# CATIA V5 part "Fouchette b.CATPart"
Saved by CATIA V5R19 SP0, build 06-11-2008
Part number: Fouchette b
Bounding box of the stored display mesh (mm): x -5 to 25, y -62.897 to 66.305, z -40 to 76.539
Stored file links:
  F:\CFAO\Hberriche\Fouchette b.CATPart
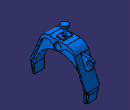
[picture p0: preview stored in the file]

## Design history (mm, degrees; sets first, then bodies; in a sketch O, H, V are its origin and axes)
Body1 (main body)
  Sketch1 on yz-plane, origin (0, 0, 0), H (0, 1, 0), V (0, 0, 1)
    line L1 (-54.7472, -20) -> (-54.7472, -40)
    point P1 (-54.7472, -20)
    point P2 (-54.7472, -40)
    point P3 (55.0096, -26.2979)
    arc A1 centre (0, -27) radius 55.1929 from (0, 28.1929) to (-54.7472, -20) ccw
    point P4 (0, -27)
    point P5 (-54.7472, -20)
    line L2 (-54.7472, -40) -> (-59.7472, -40)
    point P6 (-59.7472, -40)
    line L3 (-59.7472, -40) -> (-63.2737, -20)
    point P7 (-63.2737, -20)
    line L4 (-63.2737, -20) -> (-32.7996, 53.0392)
    point P8 (-32.7996, 53.0392)
    line L5 (-32.7996, 53.0392) -> (0, 53.0392)
    point P9 (-32.7996, 53.0392)
    axis line L6 (0, 72.9256) -> (0, -136.9568)
    point P10 (0, 72.9256)
    point P12 (0, 53.0392)
    point P13 (0, 28.1929)
    point P14 (0, 0)
    construction line L7 through (0, 0) direction (0, 1)
    point P17 (54.7472, -20)
    point P18 (54.7472, -40)
    point P20 (54.7472, -20)
    point P21 (59.7472, -40)
    point P22 (63.2737, -20)
    point P23 (32.7996, 53.0392)
    point P24 (32.7996, 53.0392)
    point P25 (0, 53.0392)
    point P26 (0, 28.1929)
    line L8 (54.7472, -20) -> (54.7472, -40)
    arc A2 centre (0, -27) radius 55.1929 from (0, 28.1929) to (54.7472, -20) cw
    line L9 (54.7472, -40) -> (59.7472, -40)
    line L10 (59.7472, -40) -> (63.2737, -20)
    line L11 (63.2737, -20) -> (32.7996, 53.0392)
    line L12 (32.7996, 53.0392) -> (0, 53.0392)
    distance P4 O = 27
    length L1 = 20
    radius A1 = 55.1929
    angle L3 L2 = 100
    length L2 = 5
    distance H L2 = 40
    distance P7 H = 20
    vertical: L1 V, L6 V
    coincidence: P4 V, P5 P1, P9 P8, P10 V, L6 P12, L6 P13, P12 P25, P13 P26, P17 P20, P23 P24
    horizontal: L2 H, L5 H
    symmetry: O P14 L6, V L7 L6, P1 P17 L6, P2 P18 L6, P5 P20 L6, P6 P21 L6, P7 P22 L6, P8 P23 L6, P9 P24 L6, P12 P25 L6, P13 P26 L6, L1 L8 L6, A1 A2 L6, L2 L9 L6, L3 L10 L6, L4 L11 L6, L5 L12 L6
  Pad1: profile Sketch1, direction (1, 0, 0), length 20
  Fillet1: radius 20, on edge [face of Pad1 from Sketch1.L4 | face of Pad1 from Sketch1.L5]; edge [face of Pad1 from Sketch1.L12 | face of Pad1 from Sketch1.L11]
  Fillet2: radius 10, on edge [face of Pad1 from Sketch1.L11 | face of Pad1 from Sketch1.L10]; edge [face of Pad1 from Sketch1.L3 | face of Pad1 from Sketch1.L4]
  Sketch2 on start face of Pad1, origin (0, 0, 0), H (0, -1, 0), V (0, 0, 1)
    axis line L1 (0, 18.2812) -> (0, -60.1212)
    point P1 (0, 18.2812)
    point P3 (-57.7472, -22)
    line L2 (-57.7472, -22) -> (-54.7472, -22)
    line L3 (-54.7472, -22) -> (-54.7472, -40)
    line L4 (-54.7472, -40) -> (-57.7472, -40)
    line L5 (-57.7472, -40) -> (-57.7472, -22)
    point P4 (-54.7472, -22)
    point P5 (-54.7472, -40)
    point P6 (-57.7472, -40)
    reference projected line E1 (-54.7472, -20) -> (-54.7472, -40) from edge [start face of Pad1 | face of Pad1 from Sketch1.L8]
    reference projected line E2 (-54.7472, -40) -> (-59.7472, -40) from edge [start face of Pad1 | face of Pad1 from Sketch1.L9]
    point P7 (57.7472, -22)
    point P8 (54.7472, -22)
    point P9 (54.7472, -40)
    point P10 (57.7472, -40)
    line L6 (57.7472, -22) -> (54.7472, -22)
    line L7 (54.7472, -22) -> (54.7472, -40)
    line L8 (54.7472, -40) -> (57.7472, -40)
    line L9 (57.7472, -40) -> (57.7472, -22)
    length L5 = 18
    length L2 = 3
    coincidence: P1 V, E1 L3, E2 L4
    vertical: L1 V, L3 V, L5 V
    horizontal: L2 H, L4 H
    symmetry: P3 P7 L1, P4 P8 L1, P5 P9 L1, P6 P10 L1, L2 L6 L1, L3 L7 L1, L4 L8 L1, L5 L9 L1
  Pad2: profile Sketch2, direction (-1, 0, 0), length 1.5
  Chamfer1: length 1, angle 45, on edge [start face of Pad1 | face of Pad2 from Sketch2.L5]; edge [start face of Pad1 | face of Pad2 from Sketch2.L9]
  Chamfer2: length 1, angle 45, on edge [face of Pad2 from Sketch2.L6 | start face of Pad1]; edge [face of Pad2 from Sketch2.L2 | start face of Pad1]
  Sketch3 on end face of Pad1, origin (20, 0, 0), H (0, 1, 0), V (0, 0, 1)
    point P1 (-57.7472, -22)
    line L1 (-57.7472, -22) -> (-54.7472, -22)
    line L2 (-54.7472, -22) -> (-54.7472, -40)
    line L3 (-54.7472, -40) -> (-57.7472, -40)
    line L4 (-57.7472, -40) -> (-57.7472, -22)
    point P2 (-54.7472, -22)
    point P3 (-54.7472, -40)
    point P4 (-57.7472, -40)
    reference projected line E1 (-54.7472, -40) -> (-54.7472, -20) from edge [face of Pad2 | end face of Pad1]
    reference projected line E2 (-59.7472, -40) -> (-54.7472, -40) from edge [face of Pad2 | end face of Pad1]
    axis line L5 (0, 14.1805) -> (0, -71.2709)
    point P5 (0, 14.1805)
    point P7 (57.7472, -22)
    point P8 (54.7472, -22)
    point P9 (54.7472, -40)
    point P10 (57.7472, -40)
    line L6 (57.7472, -22) -> (54.7472, -22)
    line L7 (54.7472, -22) -> (54.7472, -40)
    line L8 (54.7472, -40) -> (57.7472, -40)
    line L9 (57.7472, -40) -> (57.7472, -22)
    length L1 = 3
    length L4 = 18
    horizontal: L1 H, L3 H
    vertical: L2 V, L4 V, L5 V
    coincidence: E1 L2, E2 L3, P5 V
    symmetry: P1 P7 L5, P2 P8 L5, P3 P9 L5, P4 P10 L5, L1 L6 L5, L2 L7 L5, L3 L8 L5, L4 L9 L5
  Pad3: profile Sketch3, direction (1, 0, 0), length 1.5
  Chamfer3: length 1, angle 45, on edge [end face of Pad1 | face of Pad3 from Sketch3.L9]; edge [end face of Pad1 | face of Pad3 from Sketch3.L4]
  Chamfer4: length 1, angle 45, on edge [face of Pad3 from Sketch3.L1 | end face of Pad1]; edge [face of Pad3 from Sketch3.L6 | end face of Pad1]
  Sketch4 on end face of Pad1, origin (20, 0, 0), H (0, 1, 0), V (0, 0, 1)
    point P1 (0, 42)
    circle A1 centre (0, 42) radius 7.5
    radius A1 = 7.5
    distance P1 H = 42
    coincidence: P1 V
  Pocket1: profile Sketch4, direction (-1, 0, 0), through (limit type 3)
  Sketch5 on end face of Pad1, origin (20, 0, 0), H (0, 1, 0), V (0, 0, 1)
    axis line L1 (0, 100.8756) -> (0, -48.8435)
    point P1 (0, 100.8756)
    line L2 (0, 53.0392) -> (-19.4732, 53.0392)
    point P3 (0, 53.0392)
    line L3 (-37.931, 40.7404) -> (-61.0345, -14.6332)
    point P4 (-61.0345, -14.6332)
    arc A1 centre (-19.4732, 33.0392) radius 20 from (-19.4732, 53.0392) to (-37.931, 40.7404) ccw
    point P5 (-19.4732, 53.0392)
    point P6 (-37.931, 40.7404)
    point P8 (0, 0)
    construction line L4 through (0, 0) direction (0, 1)
    line L5 (-61.0345, -14.6332) -> (-58.2658, -15.7883)
    point P11 (-58.2658, -15.7883)
    line L6 (-58.2658, -15.7883) -> (-37.1225, 34.887)
    point P12 (0, 69.6951)
    point P13 (-28.4603, 55.6484)
    point P14 (0, 0)
    construction line L7 through (0, 0) direction (0, 1)
    point P17 (0, 100.8756)
    point P18 (0, 53.0392)
    point P19 (61.0345, -14.6332)
    point P20 (19.4732, 53.0392)
    point P21 (37.931, 40.7404)
    point P23 (0, 0)
    point P24 (58.2658, -15.7883)
    point P25 (0, 69.6951)
    point P26 (28.4603, 55.6484)
    line L8 (0, 53.0392) -> (19.4732, 53.0392)
    line L9 (37.931, 40.7404) -> (61.0345, -14.6332)
    arc A2 centre (19.4732, 33.0392) radius 20 from (19.4732, 53.0392) to (37.931, 40.7404) cw
    line L10 (61.0345, -14.6332) -> (58.2658, -15.7883)
    line L11 (58.2658, -15.7883) -> (37.1225, 34.887)
    arc A3 centre (0, 42) radius 10 from (-8.5986, 36.8946) to (8.5986, 36.8946) ccw
    point P27 (0, 42)
    arc A4 centre (-22.3563, 28.7261) radius 16 from (-8.5986, 36.8946) to (-37.1225, 34.887) ccw
    arc A5 centre (22.3563, 28.7261) radius 16 from (8.5986, 36.8946) to (37.1225, 34.887) cw
    circle A6 centre (0, 42) radius 7.5
    length L5 = 3
    length L3 = 60
    radius A4 = 16
    radius A5 = 16
    radius A3 = 10
    distance P27 H = 42
    radius A6 = 7.5
    coincidence: P1 V, P3 L1, L3, L2, P12 L1, P3 P18, P12 P25, P27 L1, L6 P13, L11 P26
    vertical: L1 V
    horizontal: L2 H
    tangency: A1 L2, A1 L3, A4 A3, A4 L6, A5 A3, A5 L11
    concentricity: A1
    symmetry: O P8 L1, V L4 L1, O P14 L4, V L7 L4, P1 P17 L4, P3 P18 L4, P4 P19 L4, P5 P20 L4, P6 P21 L4, P8 P23 L4, P11 P24 L4, P12 P25 L4, P13 P26 L4, L2 L8 L4, L3 L9 L4, A1 A2 L4, L5 L10 L4, L6 L11 L4
    perpendicularity: L5 L3
    parallelism: L6 L3
  Pad4: profile Sketch5, direction (1, 0, 0), length 5
  Pad5: profile Sketch5, direction (-1, 0, 0), length 25
  Fillet3: radius 10, on edge [end face of Pad1 | face of Pad4 from Sketch5.L5]; edge [end face of Pad1 | face of Pad4 from Sketch5.L10]
  Fillet4: radius 10, on edge [face of Pad5 from Sketch5.L5 | start face of Pad1]; edge [start face of Pad1 | face of Pad5 from Sketch5.L10]
  Sketch6 on face of Pad5, origin (0, 46.7848, 19.52), H (-1, 0, 0), V (0, -0.3851, 0.9229)
    point P1 (-10, 4.9933)
    reference projected line E1 (5, -37.0067) -> (5, 22.9933) from edge [end face of Pad5 | face of Pad5]
    reference projected line E2 (0, 22.9933) -> (-20, 22.9933) from edge [face of Pad5 | face of Pad5]
    distance P1 E1 = 15
    distance E2 P1 = 18
  Plane1: type OffsetPt, RefPlane yz-plane, RefPoint Sketch6
  Sketch7 on Plane1, origin (10, 0, 0), H (0, 1, 0), V (0, 0, 1)
    line L1 (37.953, 40.6877) -> (49.0125, 14.1806)
    point P1 (37.953, 40.6877)
    reference projected line E1 (61.0345, -14.6332) -> (37.931, 40.7404) from edge [face of Pad5 | end face of Pad4]
    line L2 (37.953, 40.6877) -> (55.5751, 40.6877)
    point P3 (37.953, 40.6877)
    point P4 (57.953, 40.6877)
    line L3 (60.0763, 39.6174) -> (67.0917, 36.081)
    point P5 (67.0917, 36.081)
    line L4 (67.0917, 36.081) -> (65.8687, 33.655)
    point P6 (67.0917, 36.081)
    point P7 (65.8687, 33.655)
    line L5 (49.0125, 14.1806) -> (60.0872, 18.8013)
    point P9 (65.8687, 33.655)
    point P10 (65.8687, 33.655)
    line L6 (60.0872, 18.8013) -> (58.9321, 21.57)
    point P11 (58.9321, 21.57)
    point P12 (58.9321, 21.57)
    point P13 (58.9321, 21.57)
    arc A1 centre (58.9904, 29.5698) radius 8 from (58.9321, 21.57) to (65.8687, 33.655) cw
    point P14 (58.9904, 29.5698)
    point P15 (65.8687, 33.655)
    arc A2 centre (55.5751, 30.6877) radius 10 from (55.5751, 40.6877) to (60.0763, 39.6174) cw
    distance P14 A1 = 8
    length L5 = 12
    distance P3 P4 = 20
    radius A2 = 10
    length L6 = 3
    coincidence: E1 L1, P6 L3, P5 P6, P3 P1, P9 L4, P12 L6, P7 P9, P12 P11, A1 P10, P15 P10, P11 P13, L2 P4, L3 P4, P10 P7
    horizontal: L2 H
    perpendicularity: L4 L3, L5 L1
    parallelism: L6 L1
    tangency: A2 L2, A2 L3
  Pad6: profile Sketch7, direction (1, 0, 0), length 2.5, mirrored extent
  Fillet5: radius 2, on edge [face of Pad5 | face of Pad6 from Sketch7.L2]
  Fillet6: radius 1, on edge [face of Pad6 from Sketch7.L5 | face of Pad5]
  Sketch8 on face of Pad5, origin (0, 0, 53.0392), H (1, 0, 0), V (0, 1, 0)
    point P1 (10, 0)
    reference projected line E1 (25, 19.4732) -> (25, 0) from edge [face of Pad5 | end face of Pad4]
    distance P1 E1 = 15
    coincidence: P1 H
  Plane2: type Tangent, Support face of Pad5, RefPoint Sketch8
  Sketch9 on Plane2, origin (0, 0, 53.0392), H (1, 0, 0), V (0, -1, 0)
    line L1 (20, 7.5) -> (0, 7.5)
    line L2 (0, 7.5) -> (0, -7.5)
    line L3 (0, -7.5) -> (20, -7.5)
    line L4 (20, -7.5) -> (20, 7.5)
    reference projected line E1 (0, 0) -> (20, 0) from edge [face of Pad5 | face of Pad5]
    reference projected point E2 (10, 0) from Sketch8
    length L1 = 20
    length L2 = 15
    distance L1 E1 = 7.5
    distance E2 L2 = 10
    horizontal: L1 H, L3 H
    vertical: L2 V, L4 V
  Pad7: profile Sketch9, direction (0, 0, 1), length 2.5
  Sketch10 on end face of Pad7, origin (0, 0, 55.5392), H (1, 0, 0), V (0, 1, 0)
    circle A1 centre (10, 0) radius 5
    point P1 (10, 0)
    reference projected point E1 (10, 0) from Sketch8
    radius A1 = 5
    coincidence: P1 H, E1 P1
  Pad8: profile Sketch10, direction (0, 0, 1), length 1
  Sketch11 on end face of Pad8, origin (0, 0, 56.5392), H (1, 0, 0), V (0, 1, 0)
    circle A1 centre (10, 0) radius 2.5
    point P1 (10, 0)
    reference projected circle E1 centre (10, 0) radius 5 from edge [face of Pad8 from Sketch10.A1 | end face of Pad8]
    radius A1 = 2.5
    coincidence: P1 H
    concentricity: E1 A1
  Pad9: profile Sketch11, direction (0, 0, 1), length 15
  Sketch12 on end face of Pad9, origin (0, 0, 71.5392), H (1, 0, 0), V (0, 1, 0)
    circle A1 centre (10, 0) radius 7.5
    point P1 (10, 0)
    reference projected circle E1 centre (10, 0) radius 5 from edge [face of Pad8 from Sketch10.A1 | end face of Pad8]
    radius A1 = 7.5
    coincidence: P1 H
    concentricity: E1 A1
  Pad10: profile Sketch12, direction (0, 0, 1), length 5
  Fillet7: radius 2, on edge [face of Pad6 from Sketch7.L3 | face of Pad6 from Sketch7.L4]
  Sketch13 on end face of Pad6, origin (12.5, 0, 0), H (0, 1, 0), V (0, 0, 1)
    point P1 (58.9904, 29.5698)
    reference projected arc E1 centre (58.9904, 29.5698) radius 8 from (65.8687, 33.655) to (58.9321, 21.57) ccw from edge [face of Pad6 from Sketch7.A1 | end face of Pad6]
    concentricity: E1 P1
  Plane3: type Tangent, Support end face of Pad6, RefPoint Sketch13
  Sketch14 on Plane3, origin (12.5, 0, 0), H (0, -1, 0), V (0, 0, 1)
    line L1 (-54.6438, 29.5698) -> (-66.8987, 29.5698)
    reference projected point E1 (-58.9904, 29.5698) from Sketch13
    horizontal: L1 H
    coincidence: E1 L1
  Plane4: type Angle, RefPlane Plane3, Direction Sketch14, Angle 90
